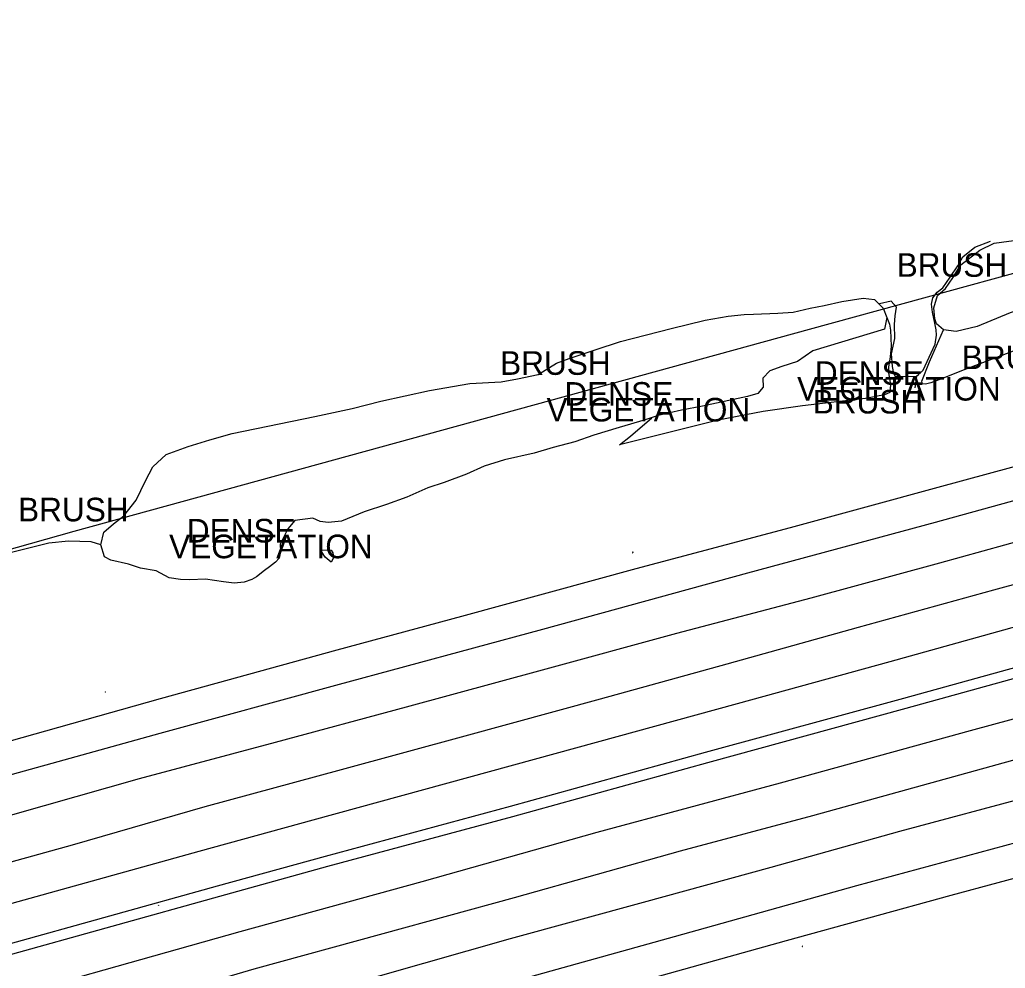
# Model space of a CAD drawing. Extents: x 2129547 to 2134906, y 657330 to 659734.
# Drawn here: x 2129941.3 to 2130233.3, y 657821.5 to 658102.6 of the extents above; entities that cross this region are included whole.
import ezdxf

# ---------------------------------------------------------------- set-up
doc = ezdxf.new("R2010")
doc.units = 0
for name, color, linetype in [('DR_X_Culvert', 7, 'Continuous'), ('HY_X_Water_Edge', 7, 'Continuous'), ('LT_X_Poles', 7, 'Continuous'), ('PM_X_Edge_Line', 7, 'Continuous'), ('PM_X_Lane_Line', 7, 'Continuous'), ('PV_X_EOP2', 7, 'Continuous'), ('PV_X_Shoulder', 7, 'Continuous'), ('RD_X_Cells', 7, 'Continuous'), ('RD_X_Concrete_Barrier', 7, 'Continuous'), ('RD_X_Fence', 7, 'Continuous'), ('RD_X_Misc_Items', 7, 'Continuous'), ('SN_X_Public', 7, 'Continuous'), ('VG_X_Shrub_Line_Lt', 7, 'Continuous'), ('VG_X_Text', 7, 'Continuous'), ('VG_X_Tree_Line_Lt', 7, 'Continuous')]:
    doc.layers.add(name, color=color, linetype=linetype)

msp = doc.modelspace()

# ---------------------------------------------------------------- linework, layer by layer
at = {"layer": 'DR_X_Culvert'}
msp.add_lwpolyline([(2130200.48, 657993.29), (2130200.73, 657996.89), (2130206.93, 657996.92), (2130206.48, 657993.54)], dxfattribs=at)
at = {"layer": 'HY_X_Water_Edge'}
for points in [[(2130206.93, 657996.92), (2130207.55, 657997.47), (2130208.95, 657998.72), (2130212.53, 658006.43), (2130212.88, 658009.07), (2130212.82, 658010.68), (2130212.41, 658012.61), (2130211.73, 658015.87), (2130211.4, 658018.33), (2130211.81, 658020.17), (2130213.04, 658021.8), (2130214.73, 658023.14), (2130216.92, 658026.26), (2130219.21, 658029.6), (2130220.69, 658032.31), (2130224.28, 658035.22), (2130228.86, 658036.98)], [(2130200.73, 657996.89), (2130200.3, 657997.74), (2130199.9, 657999.82), (2130199.57, 658003.53), (2130200.58, 658008.15), (2130200.45, 658012.21), (2130200.67, 658014.79), (2130201.07, 658017.37), (2130199.44, 658019.18), (2130195.97, 658018.39)]]:
    msp.add_lwpolyline(points, dxfattribs=at)
at = {"layer": 'LT_X_Poles'}
msp.add_lwpolyline([(2130122.93, 657944.94), (2130122.85, 657944.65), (2130122.97, 657944.65)], dxfattribs=at)
msp.add_circle((2130122.89, 657944.8), 0.065, dxfattribs=at)
at = {"layer": 'PM_X_Edge_Line'}
for points in [[(2129783, 657797.65), (2129820.8, 657807.78), (2129922.27, 657836.17), (2129994.45, 657856.25), (2130028.21, 657865.49), (2130093.84, 657883.42), (2130153.98, 657899.99), (2130199.12, 657912.39), (2130249.09, 657926.31), (2130302.49, 657941.01), (2130341.07, 657951.58), (2130345.17, 657952.7), (2130404.65, 657969.17), (2130458.77, 657984.04), (2130511.95, 657998.61), (2130564.35, 658012.89), (2130611.28, 658025.79), (2130665.46, 658040.53), (2130717.36, 658054.84), (2130762.68, 658067.32), (2130806.63, 658079.2), (2130851.4, 658091.68), (2130882.88, 658100.31), (2130891, 658102.57)], [(2129782.31, 657770.56), (2129838.02, 657785.8), (2129918.94, 657807.73), (2130006.57, 657832.43), (2130060.5, 657847.21), (2130112.38, 657861.87), (2130166.66, 657876.43), (2130223.01, 657891.92), (2130282.32, 657908.07), (2130309.12, 657915.87), (2130347.7, 657926.43), (2130352.07, 657927.63), (2130411.57, 657944.11), (2130465.65, 657958.97), (2130518.8, 657973.53), (2130571.22, 657987.81), (2130618.14, 658000.71), (2130672.33, 658015.45), (2130724.27, 658029.78), (2130769.53, 658042.24), (2130813.51, 658054.13), (2130850.23, 658064.39), (2130880.11, 658072.6), (2130898.43, 658077.6)], [(2129783.9, 657836.03), (2129845.86, 657853.1), (2129914.14, 657872.06), (2129982.95, 657891.18), (2130034.97, 657905.36), (2130096.22, 657921.98), (2130157.01, 657938.72), (2130212.56, 657953.66), (2130267.72, 657968.86), (2130293.3, 657975.86), (2130314.89, 657981.71), (2130331.88, 657986.43), (2130357.23, 657993.47), (2130407.01, 658008.01), (2130461.65, 658024.51), (2130507.73, 658038.43), (2130546.43, 658050.14)], [(2129781.33, 657733.06), (2129822.4, 657744.28), (2129902.75, 657766.7), (2130016.9, 657798.42), (2130084.9, 657816.89), (2130135.24, 657830.94), (2130189.26, 657846.05), (2130240.42, 657859.85), (2130282.16, 657871.36), (2130318.23, 657881.32), (2130332.01, 657885.16), (2130356.78, 657892.02), (2130375.64, 657897.24), (2130413.2, 657907.59), (2130448.12, 657917.07), (2130481.79, 657926.44), (2130514.96, 657935.23), (2130533.56, 657939.51)]]:
    msp.add_lwpolyline(points, dxfattribs=at)
at = {"layer": 'PM_X_Lane_Line'}
for points in [[(2129783.61, 657823.91), (2129810.31, 657831.3), (2129849.13, 657842.04), (2129899.17, 657855.99), (2129939.24, 657867.08), (2129976.77, 657877.74), (2130017.08, 657888.49), (2130055.92, 657899.02), (2130096.18, 657909.94), (2130136.01, 657920.82), (2130175.79, 657931.24), (2130213.92, 657941.68), (2130252.44, 657952.34), (2130296.32, 657964.4), (2130319.63, 657970.79), (2130334.89, 657975.01), (2130359.14, 657981.71), (2130397.93, 657992.31), (2130437.8, 658003.41), (2130477.78, 658014.39), (2130517.26, 658025.11), (2130555.6, 658035.62)], [(2129783.29, 657810.14), (2129804.42, 657815.9), (2129840.99, 657826.02), (2129880.02, 657836.71), (2129920.48, 657848.01), (2129956.91, 657858.04), (2129996.24, 657869.42), (2130036.61, 657880.37), (2130073.22, 657890.36), (2130113.36, 657901.36), (2130150.86, 657911.7), (2130189.83, 657922.56), (2130229.83, 657933.62), (2130267.33, 657943.86), (2130299.45, 657952.54), (2130338.02, 657963.15), (2130345.77, 657965.28), (2130383.32, 657975.73), (2130422.46, 657986.54), (2130460.74, 657996.93), (2130499.23, 658007.56), (2130538.61, 658018.28)], [(2129781.97, 657758.13), (2129790.58, 657760.5), (2129829.56, 657771.14), (2129869.63, 657781.89), (2129945.41, 657803.63), (2129982.9, 657813.16), (2130010.71, 657821.32), (2130048.97, 657831.8), (2130087.83, 657842.51), (2130137.07, 657856.3), (2130176.24, 657866.81), (2130213.39, 657877.02), (2130252.97, 657888.01), (2130290.12, 657898.33), (2130312.18, 657904.29), (2130329.72, 657909.17), (2130350.72, 657914.99), (2130369.2, 657920.1), (2130409.79, 657931.31), (2130447.91, 657941.44), (2130484.91, 657951.63), (2130526.03, 657962.85), (2130563.47, 657973.17)], [(2130557.28, 657959.92), (2130518.18, 657949.28), (2130479.22, 657938.42), (2130439.87, 657927.68), (2130400.48, 657916.61), (2130360.47, 657905.46), (2130353.72, 657903.61), (2130321.86, 657894.87), (2130315.15, 657893.02), (2130282.49, 657883.85), (2130241.71, 657872.68), (2130201.93, 657862), (2130163.85, 657851.39), (2130126, 657840.99), (2130086.64, 657830.21), (2130048.06, 657819.28), (2130006.64, 657808.18), (2129969.33, 657798.07), (2129930.34, 657787.23), (2129890.21, 657775.75), (2129850.72, 657764.54), (2129813.2, 657754.11), (2129781.62, 657745.43)]]:
    msp.add_lwpolyline(points, dxfattribs=at)
at = {"layer": 'PV_X_EOP2'}
for points in [[(2129783, 657797.65), (2129820.8, 657807.78), (2129922.27, 657836.17), (2129994.45, 657856.25), (2130028.21, 657865.49), (2130093.84, 657883.42), (2130153.98, 657899.99), (2130199.12, 657912.39), (2130249.09, 657926.31), (2130302.49, 657941.01), (2130341.07, 657951.58), (2130345.17, 657952.7), (2130404.65, 657969.17), (2130458.77, 657984.04), (2130511.95, 657998.61), (2130564.35, 658012.89), (2130611.28, 658025.79), (2130665.46, 658040.53), (2130717.36, 658054.84), (2130762.68, 658067.32), (2130806.63, 658079.2), (2130851.4, 658091.68), (2130882.88, 658100.31), (2130891, 658102.57)], [(2129782.31, 657770.56), (2129838.02, 657785.8), (2129918.94, 657807.73), (2130006.57, 657832.43), (2130060.5, 657847.21), (2130112.38, 657861.87), (2130166.66, 657876.43), (2130223.01, 657891.92), (2130282.32, 657908.07), (2130309.12, 657915.87), (2130347.7, 657926.43), (2130352.07, 657927.63), (2130411.57, 657944.11), (2130465.65, 657958.97), (2130518.8, 657973.53), (2130571.22, 657987.81), (2130618.14, 658000.71), (2130672.33, 658015.45), (2130724.27, 658029.78), (2130769.53, 658042.24), (2130813.51, 658054.13), (2130850.23, 658064.39), (2130880.11, 658072.6), (2130898.43, 658077.6)], [(2129783.9, 657836.03), (2129845.86, 657853.1), (2129914.14, 657872.06), (2129982.95, 657891.18), (2130034.97, 657905.36), (2130096.22, 657921.98), (2130157.01, 657938.72), (2130212.56, 657953.66), (2130267.72, 657968.86), (2130293.3, 657975.86), (2130314.89, 657981.71), (2130331.88, 657986.43), (2130357.23, 657993.47), (2130407.01, 658008.01), (2130461.65, 658024.51), (2130507.73, 658038.43), (2130546.43, 658050.14)], [(2129781.33, 657733.06), (2129822.4, 657744.28), (2129902.75, 657766.7), (2130016.9, 657798.42), (2130084.9, 657816.89), (2130135.24, 657830.94), (2130189.26, 657846.05), (2130240.42, 657859.85), (2130282.16, 657871.36), (2130318.23, 657881.32), (2130332.01, 657885.16), (2130356.78, 657892.02), (2130375.64, 657897.24), (2130413.2, 657907.59), (2130448.12, 657917.07), (2130481.79, 657926.44), (2130514.96, 657935.23), (2130533.56, 657939.51)]]:
    msp.add_lwpolyline(points, dxfattribs=at)
at = {"layer": 'PV_X_Shoulder'}
for points in [[(2129784.13, 657845.78), (2129820.77, 657855.85), (2129911.85, 657881.4), (2129982.97, 657901.46), (2130035.32, 657915.88), (2130072.23, 657925.85), (2130123.9, 657939.97), (2130169.63, 657952.07), (2130213.34, 657964.08), (2130250.16, 657974.02), (2130290.75, 657985.53), (2130329.29, 657996.26), (2130330.56, 657996.61), (2130370.76, 658007.9), (2130412.81, 658020.38), (2130453.6, 658032.45), (2130494.01, 658044.69), (2130534.58, 658056.98)], [(2129781.12, 657723.15), (2129791.26, 657725.96), (2129847.2, 657740.42), (2129910.54, 657757.22), (2129956.62, 657769.85), (2130017.82, 657787.52), (2130067.36, 657801.54), (2130112.53, 657814.1), (2130168.41, 657829.75), (2130217.23, 657843.2), (2130272.91, 657858.21), (2130320.81, 657871.55), (2130356.56, 657881.59), (2130359.33, 657882.35), (2130366.22, 657884.23)]]:
    msp.add_lwpolyline(points, dxfattribs=at)
at = {"layer": 'RD_X_Cells'}
msp.add_lwpolyline([(2130173.05, 657827.98), (2130173.11, 657827.95), (2130173.18, 657827.98), (2130173.18, 657828.06), (2130173.11, 657828.1), (2130173.05, 657828.06), (2130173.05, 657827.98)], dxfattribs=at)
at = {"layer": 'RD_X_Concrete_Barrier'}
for points in [[(2130565.99, 658001.27), (2130519.98, 657988.71), (2130477.65, 657977.23), (2130423.68, 657962.34), (2130372.81, 657948.31), (2130344.01, 657940.43), (2130324.59, 657935.12), (2130305.44, 657929.81), (2130253.45, 657915.37), (2130203.07, 657901.49), (2130144.32, 657885.41), (2130086.58, 657869.4), (2130031.8, 657854.67), (2129999.77, 657845.79), (2129936.01, 657828.01), (2129863.42, 657807.87), (2129795.91, 657789.82), (2129782.73, 657786.14)], [(2129782.65, 657783), (2129796.7, 657786.92), (2129864.21, 657804.98), (2129936.81, 657825.12), (2130000.57, 657842.9), (2130032.59, 657851.78), (2130087.37, 657866.51), (2130145.12, 657882.52), (2130203.86, 657898.59), (2130254.25, 657912.48), (2130306.25, 657926.92), (2130325.39, 657932.23), (2130344.78, 657937.53), (2130373.6, 657945.42), (2130424.48, 657959.44), (2130478.44, 657974.34), (2130520.77, 657985.82), (2130566.78, 657998.38)]]:
    msp.add_lwpolyline(points, dxfattribs=at)
at = {"layer": 'RD_X_Fence'}
for points in [[(2130276.74, 658038.66), (2130175.12, 658010.79), (2129957.33, 657950.93)], [(2129957.33, 657950.93), (2129871.87, 657926.81), (2129835.71, 657925.52), (2129813.7, 657924.61), (2129796.85, 657923.3), (2129786.02, 657920.42)]]:
    msp.add_lwpolyline(points, dxfattribs=at)
at = {"layer": 'RD_X_Misc_Items'}
msp.add_lwpolyline([(2130033.52, 657941.85), (2130031.83, 657943.33), (2130030.7, 657945.03), (2130030.65, 657945.28), (2130030.89, 657945.49), (2130033.57, 657945.44), (2130034.01, 657944.56), (2130034.22, 657943.34), (2130034.1, 657942.72)], close=True, dxfattribs=at)
at = {"layer": 'SN_X_Public'}
for p, q in [((2129966.66, 657903.38), (2129966.58, 657903.36)), ((2129966.65, 657903.46), (2129966.68, 657903.3)), ((2129982.42, 657840.16), (2129982.34, 657840.14)), ((2129982.4, 657840.23), (2129982.44, 657840.08))]:
    msp.add_line(p, q, dxfattribs=at)
at = {"layer": 'VG_X_Shrub_Line_Lt'}
for points in [[(2130198.14, 658014.3), (2130199, 658012.34), (2130199.24, 658010.61), (2130199.49, 658005.8), (2130199.14, 658002.65), (2130198.64, 657999.59), (2130198.69, 657998.06), (2130199.22, 657994.37), (2130199.05, 657992.09), (2130197.49, 657991.37), (2130191.88, 657990.36), (2130173.22, 657988.12), (2130161.51, 657986.45), (2130148.22, 657983.96), (2130118.96, 657976.56), (2130122.19, 657979.17), (2130128.57, 657984.64)], [(2130265.59, 658014.49), (2130251.84, 658010.32), (2130236.4, 658004.62), (2130220.27, 657998.48), (2130215.14, 657996.5), (2130211.21, 657995), (2130209.68, 657994.58), (2130208.73, 657994.71), (2130208.58, 657995.44), (2130210.79, 658001.16), (2130214.98, 658010.69)], [(2129965.35, 657946.95), (2129962.5, 657947.9), (2129955.71, 657948.06), (2129949.9, 657947.47), (2129918.52, 657939.71), (2129913.49, 657939.26), (2129910.07, 657937.68), (2129900.08, 657934.8), (2129891.95, 657932.28), (2129883.22, 657930.38), (2129876.93, 657929.22), (2129870.89, 657928.31), (2129862.73, 657927.39), (2129855.87, 657927.06), (2129846.36, 657926.77), (2129844.16, 657926.68), (2129841.45, 657927.72), (2129839.11, 657929.88), (2129838.95, 657932.29), (2129840.82, 657936.81), (2129844.26, 657938.94), (2129846.07, 657941.32)]]:
    msp.add_lwpolyline(points, dxfattribs=at)
at = {"layer": 'VG_X_Tree_Line_Lt'}
msp.add_lwpolyline([(2130281.15, 658021.92), (2130272.03, 658020.82), (2130262.88, 658020.66), (2130250.06, 658018.74), (2130240.57, 658017.58), (2130234.72, 658015.7), (2130224.97, 658011.71), (2130218.74, 658010.15), (2130214.98, 658010.69), (2130212.91, 658012.47), (2130212.41, 658013.96), (2130212.12, 658017.16), (2130213.22, 658020.86), (2130215.55, 658022.97), (2130217.74, 658026.04), (2130220.14, 658029.97), (2130225.73, 658034.24), (2130229.94, 658036.34), (2130238.01, 658037.49), (2130253.22, 658042.08), (2130273.18, 658052.15)], dxfattribs=at)
msp.add_lwpolyline([(2130176.29, 658004.47), (2130171.69, 658001.3), (2130167.1, 657999.8), (2130163.48, 657998.55), (2130161.47, 657996.36), (2130161.54, 657993.7), (2130159.93, 657991.8), (2130156.86, 657990.93), (2130143.55, 657988.01), (2130137.35, 657986.9), (2130130.48, 657985.25), (2130126.6, 657984), (2130118.93, 657981.75), (2130111.34, 657979.42), (2130105.75, 657977.53), (2130099.34, 657975.77), (2130093.74, 657974.17), (2130084.95, 657972.2), (2130078.86, 657970.32), (2130073.7, 657967.92), (2130067.08, 657965.43), (2130062.19, 657963.87), (2130055.98, 657961.13), (2130049.95, 657958.97), (2130043.31, 657956.75), (2130036.61, 657953.96), (2130032.7, 657953.6), (2130030.34, 657953.93), (2130028.18, 657954.88), (2130022.81, 657954.17), (2130020.74, 657951.73), (2130018.41, 657947.14), (2130018.58, 657945.05), (2130018.15, 657943.06), (2130017.08, 657941.79), (2130015.27, 657940.44), (2130013.85, 657939.33), (2130011.43, 657937.45), (2130010.05, 657936.69), (2130007.76, 657935.95), (2130004.81, 657935.63), (2130001.64, 657936.03), (2129996.36, 657936.84), (2129991.71, 657936.57), (2129988.88, 657936.69), (2129985.58, 657937.15), (2129981.75, 657939.24), (2129977.05, 657940.03), (2129973.54, 657941.23), (2129968.3, 657942.46), (2129966.46, 657943.37), (2129965.34, 657946.99), (2129966.17, 657950.68), (2129969.1, 657953.21), (2129972.14, 657955.61), (2129975.84, 657960.19), (2129978.57, 657965.95), (2129980.71, 657970.06), (2129984.7, 657973.75), (2129991.18, 657976.12), (2129997.6, 657978.06), (2130004.21, 657979.99), (2130028.76, 657984.99), (2130039.82, 657987.38), (2130048.26, 657989.55), (2130062.73, 657992.72), (2130074.62, 657994.8), (2130083.93, 657995.22), (2130088.76, 657996.16), (2130094.88, 657997.48), (2130100.34, 658000.84), (2130104.08, 658002.17), (2130111.75, 658004.75), (2130119.23, 658007.18), (2130134.3, 658011.12), (2130144.37, 658013.5), (2130151.17, 658014.71), (2130155.92, 658015.19), (2130158.63, 658015.28), (2130165.86, 658015.57), (2130170.47, 658015.89), (2130175.47, 658017.14), (2130179.57, 658017.88), (2130184.85, 658019.03), (2130191.13, 658020.08), (2130194.49, 658019.64), (2130197.07, 658017.05), (2130198.14, 658014.3), (2130197.47, 658010.91)], close=True, dxfattribs=at)

# ---------------------------------------------------------------- texts
at = {"layer": 'VG_X_Text'}
for s, p in [('BRUSH', (2130201.08, 658026.39)), ('BRUSH', (2130220.39, 657999.03)), ('BRUSH', (2130083.61, 657997.34)), ('DENSE', (2130176.85, 657994.38)), ('VEGETATION', (2130171.59, 657989.72)), ('DENSE', (2130102.63, 657988.18)), ('BRUSH', (2130176.21, 657985.89)), ('VEGETATION', (2130097.37, 657983.52)), ('BRUSH', (2129940.8, 657953.92)), ('DENSE', (2129990.79, 657947.66)), ('VEGETATION', (2129985.54, 657943))]:
    msp.add_text(s, height=7, dxfattribs=at).set_placement(p)

doc.saveas('drawing.dxf')
